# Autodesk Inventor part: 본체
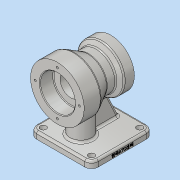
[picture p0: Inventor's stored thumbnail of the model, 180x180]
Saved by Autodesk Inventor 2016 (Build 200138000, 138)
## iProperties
Created: 2019-01
Part Number: 본체
Material: 알루미늄 6061
Document SubType Name: Modeling
Designer: Administrator
Density: 2.7 g/cm^3
Appearance: 알루미늄 - 평지
Mass: 898.821 g
Surface Area: 600.961 cm^2
Volume: 332.897 cm^3
Author: Administrator
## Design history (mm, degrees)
sketch "스케치1"
  geometry: L1 (-46, -46)-(46, -46); L2 (46, -46)-(46, 46); L3 (46, 46)-(-46, 46); L4 (-46, 46)-(-46, -46); L5 (-46, -46)-(46, 46); L6 (46, -46)-(-46, 46); 1 further point
  constraints: 12 end point, 2 midpoint, 2 parallel, 1 horizontal, 1 perpendicular
  dimensions: "d0" = 92 distance of L3.end L2.end; "d1" = 92 distance of L2.end L1.end
extrude "돌출1" new body sketch "스케치1" distance "d2" = 10; taper "d3" = 0 deg
sketch "스케치2"
  geometry: L1 (-46, 0)-(-51, 0); L2 (-51, 0)-(-51, 80); L3 (-71.125, 80)-(60.875, 80); L4 (-51, 80)-(-51, 120); L5 (-51, 120)-(-26, 120); L6 (-26, 120)-(-5.215, 108); L7 (-5.215, 108)-(8.126, 108); L8 (8.126, 108)-(14, 115); L9 (14, 115)-(29, 115); L10 (29, 115)-(29, 80); 1 further point
  constraints: 20 end point, 4 horizontal, 2 perpendicular, 2 point on line, 1 parallel, 1 vertical
  dimensions: "d4" = 5 distance of L1.start L1.end; "d5" = 80 distance of L1.end L2.end; "d6" = 40 distance of L2.end L4.end; "d7" = 25 distance of L4.end L5.end; "d11" = 30 deg angle of L6 L7; "d13" = 80 distance between parallel lines of L10 L4; "d15" = 50 deg angle of L8 L7; "d16" = 56 diameter of L7 L3; "d17" = 15 distance of L8.end L9.end; "d18" = 35 distance of L9.end L10.end
revolve "회전1" sketch "스케치2" stored, may be unused: angle "d19" = 90 deg
fillet "모깎기1" dims "d20" = 10
sketch "스케치3"
  geometry: L1 (-46, 36)-(-46, -36) reference; L2 (-36, -46)-(36, -46) reference; C1 r 16 at (0, -16); 1 further point
  constraints: 1 centre point
  dimensions: "d21" = 16 radius of C1; "d22" = 46 distance from line of C1.centre L1; "d23" = 30 distance from line of C1.centre L2
extrude "돌출2" join sketch "스케치3" stored distance "d24" = 10; taper "d25" = 0 deg
sketch "스케치4"
  geometry: L1 (46, 10)-(46, 0) reference; L2 (36, 10)-(46, 10) reference; L3 (46, 10)-(36, 10); L4 (36, 10)-(28.475, 26.136); 1 further point
  constraints: 4 end point, 1 perpendicular
  dimensions: "d26" = 10 distance of L1.start L2.start (derived); "d27" = 25 deg angle of L4 L1
feature "리브1" sketch "스케치4" dims "d28" = 1, "d29" = 10, "d30" = 0, "d31" = 0, "d32" = 1, "d33" = 1
sketch "스케치5"
  geometry: L1 (-71, 80)-(52, 80); L2 (-51, 40)-(-51, 120) reference; L3 (-51, 80)-(-51, 106); L4 (-51, 106)-(-31, 106); L5 (-31, 106)-(-31, 96); L6 (-31, 96)-(12, 96); L7 (12, 96)-(12, 100); L8 (14, 45.359)-(14, 115) reference; L9 (12, 100)-(29, 100); L10 (29, 45)-(29, 115) reference; L11 (-51, 80)-(29, 80); L12 (29, 100)-(29, 80); 1 further point
  constraints: 18 end point, 5 perpendicular, 2 midpoint, 2 point on line, 1 collinear, 1 horizontal, 1 parallel
  dimensions: "d34" = 26 distance of L3.start L3.end; "d35" = 20 distance of L3.end L4.end; "d36" = 32 diameter of L6 L1; "d37" = 40 diameter of L9 L1; "d38" = 17 distance between parallel lines of L7 L10
revolve "회전2" sketch "스케치5" stored, may be unused: angle "d39" = 90 deg
chamfer "모따기1" distance "d40" = 1; stored, may be unused: second distance "d41" = 2, angle "d42" = 45 deg
fillet "모깎기2" dims "d43" = 0.6
fillet "모깎기3" dims "d44" = 1
sketch "스케치6"
  geometry: L1 (0, 0)-(0, 33); C1 r 27 at (0, 0) reference; 1 further point
  constraints: 2 end point, 1 vertical
  dimensions: "d45" = 33 distance of L1.start L1.end
hole "구멍1" sketch "스케치6" at (0, 33) diameter "d46" = 3.242; stored, may be unused: countersink angle "d50" = 90 deg, drill point angle "d52" = 118 deg; dims "d47" = 9, "d48" = 4, "d49" = 2, "d51" = 11
sketch "스케치7"
  geometry: L1 (0, 0)-(0, -27.5); C1 r 21 at (0, 0) reference; 1 further point
  constraints: 2 end point, 1 vertical
  dimensions: "d56" = 27.5 distance of L1.start L1.end
hole "구멍2" sketch "스케치7" at (0, -27.5) diameter "d57" = 3.242; stored, may be unused: countersink angle "d61" = 90 deg, drill point angle "d63" = 118 deg; dims "d58" = 9, "d59" = 4, "d60" = 2, "d62" = 11
sketch "스케치8"
  geometry: L1 (-5, -0.801)-(-5, 36) reference; L2 (-5, 36)-(5, 36) reference; L3 (5, 36)-(5, -0.801) reference; L4 (-36, -46)-(36, -46) reference; L5 (46, -36)-(46, 36) reference; L6 (36, 46)-(-36, 46) reference; L7 (-46, 36)-(-46, -36) reference; A1 r 16 centre (0, -16) between (-5, -0.801) and (5, -0.801) reference; A2 r 10 centre (36, -36) between (36, -46) and (46, -36) reference; A3 r 10 centre (36, 36) between (46, 36) and (36, 46) reference; A4 r 10 centre (-36, 36) between (-36, 46) and (-46, 36) reference; A5 r 10 centre (-36, -36) between (-46, -36) and (-36, -46) reference; 1 further point
hole "구멍3" sketch "스케치8" at (-36, -36), (-36, 36), (36, 36), (36, -36) diameter "d67" = 9; stored, may be unused: countersink angle "d71" = 90 deg, drill point angle "d73" = 118 deg; dims "d68" = 9, "d69" = 4, "d70" = 2, "d72" = 11
fillet "모깎기4" dims "d74" = 3
fillet "모깎기5" dims "d75" = 3
fillet "모깎기6" dims "d76" = 3
fillet "모깎기7" dims "d77" = 3
sketch "스케치9"
  geometry: L1 (0, 0)-(0, 72) reference; L2 (-7, -10)-(0, -10) reference; 2 further points
  constraints: 1 other
  dimensions: "d78" = 4 distance from line of L1 point (-4, 36); "d79" = 46 distance from line of L2 point (-4, 36)
feature "엠보싱1" sketch "스케치9" dims "d0" = 92, "d1" = 92, "d80" = 0.5, "d81" = 0
feature "분할1"
node "솔리드1"
pattern_circular "원형 패턴1" dims angle "d54" = 360 deg
pattern_circular "원형 패턴2" dims angle "d65" = 360 deg
node "투영된 루프1"
